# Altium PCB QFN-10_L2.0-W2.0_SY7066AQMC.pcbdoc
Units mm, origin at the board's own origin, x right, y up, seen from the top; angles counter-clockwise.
Board outline 15.2 x 14.94 mm, 2 copper layers (Top Layer, Bottom Layer), stack 0 mm thick; 1 components, 0 nets, 10 pads, 0 vias.
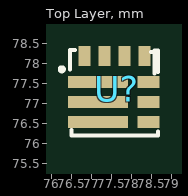
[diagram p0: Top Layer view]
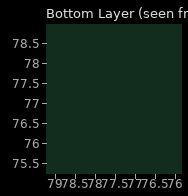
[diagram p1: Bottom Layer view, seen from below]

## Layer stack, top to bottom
Top Layer: signal copper (thickness not stored)
Bottom Layer: signal copper (thickness not stored)

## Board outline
85.047,69.85 69.85,69.85 69.85,84.79 85.047,84.79

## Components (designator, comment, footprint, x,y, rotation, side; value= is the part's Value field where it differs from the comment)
U? "" QFN-10_L2.0-W2.0_SY7066AQMC 77.62,77.365 r0 top

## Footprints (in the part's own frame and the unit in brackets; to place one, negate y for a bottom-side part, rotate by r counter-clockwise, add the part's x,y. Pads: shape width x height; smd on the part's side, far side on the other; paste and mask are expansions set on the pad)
QFN-10_L2.0-W2.0_SY7066AQMC [mm]
  rect 1.5x0.3 smd: 1(-0.467,0.175) 2(-0.467,-0.325) 3(-0.467,-0.825)
  rect 0.55x0.3 smd: 4(0.802,-0.825) 5(0.802,-0.325) 6(0.802,0.175)
  rect 0.3x0.5 smd: 7(0.698,0.825) 8(0.198,0.825) 9(-0.302,0.825) 10(-0.802,0.825)
  silkscreen extent -1.42,-1.17 1.04,0.97

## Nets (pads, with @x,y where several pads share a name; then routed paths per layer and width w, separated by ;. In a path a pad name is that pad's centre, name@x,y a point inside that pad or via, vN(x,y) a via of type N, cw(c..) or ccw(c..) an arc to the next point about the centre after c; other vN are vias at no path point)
pads on no net: U?.1 U?.2 U?.3 U?.4 U?.5 U?.6 U?.7 U?.8 U?.9 U?.10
